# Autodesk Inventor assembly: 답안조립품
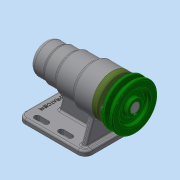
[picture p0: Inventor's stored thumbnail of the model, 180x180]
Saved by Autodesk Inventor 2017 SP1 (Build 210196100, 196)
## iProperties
Part Number: 답안조립품
Material: 일반
Document SubType Name: Assembly
Designer: MRC
Author: MRC
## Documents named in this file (12)
- C:\Users\MRC\Desktop\711009V1003\답안조립품.iam
- C:\Users\MRC\Desktop\711009V1003\본체.ipt
- C:\Users\MRC\Desktop\711009V1003\V벨트풀리.ipt
- C:\Users\MRC\Desktop\711009V1003\멈춤나사 M3.ipt
- C:\Users\MRC\Desktop\711009V1003\베어링 6004.ipt
- C:\Users\MRC\Desktop\711009V1003\베어링 51202.ipt
- C:\Users\MRC\Desktop\711009V1003\볼트 M4.ipt
- C:\Users\MRC\Desktop\711009V1003\어댑터슬리브.ipt
- C:\Users\MRC\Desktop\711009V1003\오일 실 20x35x7.ipt
- C:\Users\MRC\Desktop\711009V1003\축.ipt
- C:\Users\MRC\Desktop\711009V1003\커버.ipt
- C:\Users\MRC\Desktop\711009V1003\키 5x5.ipt
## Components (1 placed, 1 different names)
1. V벨트풀리:1
